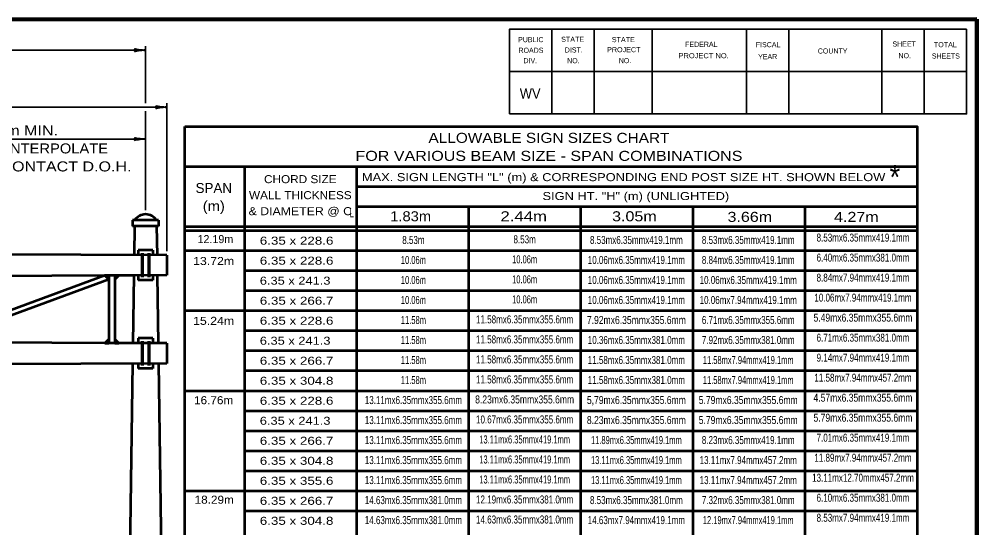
# Model space of a CAD drawing. Extents: x -34 to 822, y -23 to 521.
# Drawn here: x 527.6 to 814.9, y 362.2 to 514.7 of the extents above; entities that cross this region are included whole.
import ezdxf
from ezdxf.enums import TextEntityAlignment as Align

# ---------------------------------------------------------------- set-up
doc = ezdxf.new("R2010")
doc.units = 0
doc.header["$LTSCALE"] = 1.2
doc.layers.add('1', color=7, linetype='Continuous', lineweight=35)
doc.layers.add('61', color=7, linetype='Continuous', lineweight=35)

msp = doc.modelspace()

# ---------------------------------------------------------------- linework, layer by layer
at = {"layer": '1', "lineweight": 158}
msp.add_line((814.9, -11.36), (814.9, 514.74), dxfattribs=at)
at = {"layer": '1', "lineweight": 13}
msp.add_line((814.9, -11.36), (814.9, 514.74), dxfattribs=at)
at = {"layer": '1'}
for p, q in [((565.548, 489.542), (565.548, 506.642)), ((98.952, 505.442), (565.548, 505.442)), ((571.95, 445.142), (571.95, 489.542)), ((565.548, 457.442), (565.548, 487.142)), ((487.338, 478.781), (565.548, 478.781))]:
    msp.add_line(p, q, dxfattribs=at)
at = {"layer": '1', "lineweight": 53}
for p, q in [((577.354, 470.549), (796.954, 470.549)), ((595.354, 295.349), (595.354, 470.549)), ((628.954, 295.349), (628.954, 470.549)), ((628.954, 464.549), (796.954, 464.549)), ((628.954, 458.549), (796.954, 458.549)), ((662.554, 295.349), (662.554, 458.549)), ((696.154, 295.349), (696.154, 458.549)), ((729.754, 295.349), (729.754, 458.549)), ((763.354, 295.349), (763.354, 458.549)), ((569.448, 454.442), (561.648, 454.442)), ((561.648, 454.442), (561.648, 452.642)), ((569.448, 454.442), (569.448, 452.642)), ((569.448, 452.642), (561.648, 452.642)), ((562.248, 452.642), (562.125, 443.991)), ((568.848, 452.642), (568.971, 443.957)), ((577.354, 452.549), (796.954, 452.549)), ((577.354, 451.349), (796.954, 451.349)), ((567.75, 445.442), (563.346, 445.442)), ((563.346, 445.442), (563.346, 443.985)), ((567.75, 445.442), (567.75, 443.963)), ((577.354, 445.349), (796.954, 445.349)), ((571.95, 443.942), (333.15, 445.142)), ((571.95, 443.942), (571.95, 437.942)), ((554.538, 437.854), (502.338, 437.592)), ((553.339, 437.848), (502.338, 419.091)), ((556.338, 437.863), (554.538, 437.854)), ((554.538, 437.854), (554.538, 417.629)), ((562.038, 437.892), (556.338, 437.863)), ((556.338, 436.663), (557.538, 437.869)), ((556.338, 437.863), (556.338, 417.62)), ((562.038, 437.892), (561.75, 417.593)), ((571.95, 437.942), (562.038, 437.892)), ((563.346, 437.899), (563.346, 436.442)), ((567.75, 437.921), (567.75, 436.442)), ((569.057, 437.927), (569.346, 417.555)), ((595.354, 439.349), (796.954, 439.349)), ((554.538, 436.654), (503.538, 417.886)), ((567.75, 436.442), (563.346, 436.442)), ((595.354, 433.349), (796.954, 433.349)), ((577.354, 427.349), (796.954, 427.349)), ((595.354, 421.349), (796.954, 421.349)), ((554.538, 417.629), (502.338, 417.892)), ((553.339, 417.636), (554.538, 417.629)), ((556.338, 417.62), (554.538, 417.629)), ((561.75, 417.593), (556.338, 417.62)), ((571.95, 417.542), (561.75, 417.593)), ((567.75, 419.042), (563.346, 419.042)), ((563.346, 419.042), (563.346, 417.585)), ((567.75, 419.042), (567.75, 417.563)), ((571.95, 417.542), (571.95, 411.542)), ((595.354, 415.349), (796.954, 415.349)), ((571.95, 411.542), (333.15, 410.342)), ((561.663, 411.49), (559.59, 265.442)), ((563.346, 411.499), (563.346, 410.042)), ((567.75, 411.521), (567.75, 410.042)), ((569.431, 411.529), (571.505, 265.442)), ((567.75, 410.042), (563.346, 410.042)), ((595.354, 409.349), (796.954, 409.349)), ((577.354, 403.349), (796.954, 403.349)), ((595.354, 397.349), (796.954, 397.349)), ((595.354, 391.349), (796.954, 391.349)), ((595.354, 385.349), (796.954, 385.349)), ((595.354, 379.349), (796.954, 379.349)), ((577.354, 373.349), (796.954, 373.349)), ((595.354, 367.349), (796.954, 367.349))]:
    msp.add_line(p, q, dxfattribs=at)
at = {"layer": '1', "lineweight": 70}
for p, q in [((564.546, 444.542), (564.546, 437.342)), ((566.55, 444.542), (566.55, 437.342)), ((564.546, 418.142), (564.546, 410.942)), ((566.55, 418.142), (566.55, 410.942))]:
    msp.add_line(p, q, dxfattribs=at)
at = {"layer": '1', "lineweight": 158}
msp.add_lwpolyline([(814.9, 514.74), (23.2, 514.64), (23.3, -11.36)], dxfattribs=at)
at = {"layer": '1'}
msp.add_lwpolyline([(92.55, 488.342), (332.25, 488.342), (571.95, 488.342)], dxfattribs=at)
at = {"layer": '1', "lineweight": 53}
for points in [[(577.354, 482.549), (796.954, 482.549), (796.954, 295.349), (577.354, 295.349)], [(554.538, 436.654), (554.538, 437.854), (553.339, 437.848)], [(557.538, 417.614), (556.338, 418.82), (556.338, 417.62), (557.538, 417.614)]]:
    msp.add_lwpolyline(points, close=True, dxfattribs=at)
for points in [[(557.538, 437.869), (556.338, 437.863), (556.338, 436.663)], [(554.538, 417.629), (554.538, 418.829), (553.339, 417.635)]]:
    msp.add_lwpolyline(points, dxfattribs=at)
msp.add_arc((565.548, 452.364), 3.878, 32.40313, 147.59686, dxfattribs=at)
at = {"layer": '1', "lineweight": 40}
for centre, major_axis, ratio, start_param, end_param in [((564.203, 505.696), (2.108, -0.211), 0.07063, 3.1407148, 5.41811), ((564.203, 505.696), (2.108, -0.211), 0.07063, 3.1407148, 5.41811), ((564.238, 505.11), (2.143, 0.187), 0.122415, 0.8963533, 3.1415927), ((564.238, 505.11), (2.143, 0.187), 0.122415, 0.8963533, 3.1415927), ((570.605, 488.596), (2.108, -0.211), 0.07063, 3.1407148, 5.41811), ((570.605, 488.596), (2.108, -0.211), 0.07063, 3.1407148, 5.41811), ((570.605, 488.596), (2.108, -0.211), 0.07063, 3.1407148, 5.41811), ((570.64, 488.01), (2.143, 0.187), 0.122415, 0.8963533, 3.1415927), ((570.64, 488.01), (2.143, 0.187), 0.122415, 0.8963533, 3.1415927), ((570.64, 488.01), (2.143, 0.187), 0.122415, 0.8963533, 3.1415927), ((564.238, 478.449), (2.143, 0.187), 0.122415, 0.8963533, 3.1415927), ((564.238, 478.449), (2.143, 0.187), 0.122415, 0.8963533, 3.1415927), ((564.203, 479.035), (2.108, -0.211), 0.07063, 3.1407148, 5.41811), ((564.203, 479.035), (2.108, -0.211), 0.07063, 3.1407148, 5.41811)]:
    msp.add_ellipse(centre, major_axis=major_axis, ratio=ratio, start_param=start_param, end_param=end_param, dxfattribs=at)
at = {"layer": '61'}
for p, q in [((687.4, 511.74), (687.4, 486.34)), ((700.1, 511.74), (700.1, 486.34)), ((717.5, 511.74), (717.5, 486.34)), ((745.8, 511.74), (745.8, 486.34)), ((758.5, 511.74), (758.5, 486.34)), ((786.4, 511.74), (786.4, 486.34)), ((799.1, 511.74), (799.1, 486.34)), ((811.8, 499.04), (674.7, 499.04))]:
    msp.add_line(p, q, dxfattribs=at)
for points in [[(811.8, 511.74), (674.7, 511.74), (674.7, 486.34)], [(811.8, 511.74), (811.8, 486.34), (674.7, 486.34)]]:
    msp.add_lwpolyline(points, dxfattribs=at)

# ---------------------------------------------------------------- texts
at = {"layer": '1'}
for s, height, width, p in [('WV', 3.048, 0.95, (677.8, 490.94)), ('6.35 x 228.6', 2.4, 1.25, (599.804, 447.126)), ('6.35 x 228.6', 2.4, 1.25, (599.804, 441.126)), ('6.35 x 241.3', 2.4, 1.2, (599.804, 435.126)), ('6.35 x 266.7', 2.4, 1.25, (599.804, 429.126)), ('6.35 x 228.6', 2.4, 1.25, (599.804, 423.126)), ('6.35 x 241.3', 2.4, 1.2, (599.804, 417.126)), ('6.35 x 266.7', 2.4, 1.25, (599.804, 411.126)), ('6.35 x 304.8', 2.4, 1.25, (599.804, 405.126)), ('6.35 x 228.6', 2.4, 1.25, (599.804, 399.126)), ('6.35 x 241.3', 2.4, 1.2, (599.804, 393.126)), ('6.35 x 266.7', 2.4, 1.25, (599.804, 387.126)), ('6.35 x 304.8', 2.4, 1.25, (599.804, 381.126)), ('6.35 x 355.6', 2.4, 1.25, (599.804, 375.126)), ('6.35 x 266.7', 2.4, 1.25, (599.804, 369.126)), ('6.35 x 304.8', 2.4, 1.25, (599.804, 363.126))]:
    msp.add_text(s, height=height, dxfattribs=dict(at, width=width)).set_placement(p)
for s, height, width, p in [('1.83m MIN.', 3, 1.2, (526.826, 479.882)), ('ALLOWABLE SIGN SIZES CHART', 3, 1.15, (686.551, 477.653)), ('FOR LESS: INTERPOLATE', 3, 1.1, (526.826, 474.482)), ('FOR VARIOUS BEAM SIZE - SPAN COMBINATIONS', 3, 1.2, (686.551, 472.253)), ('TO MAX. OR CONTACT D.O.H.', 3, 1.2, (526.826, 469.082)), ('MAX. SIGN LENGTH "L" (m) & CORRESPONDING END POST SIZE HT. SHOWN BELOW', 2.4, 1.2, (708.936, 466.171)), ('*', 7.2, 0.85, (790.32, 463.792)), ('CHORD SIZE', 2.4, 1.1, (611.96, 465.568)), ('WALL THICKNESS', 2.4, 1.1, (611.96, 460.768)), ('SIGN HT. "H" (m) (UNLIGHTED)', 2.4, 1.2, (712.609, 460.502)), ('(m)', 3, 1.1, (586.003, 457.221)), ('& DIAMETER @ C', 2.4, 1.15, (611.96, 455.968)), ('L', 2.4, 0.75, (627.392, 455.332)), ('1.83m', 3, 1.1, (645.057, 454.14)), ('2.44m', 3, 1.25, (678.97, 454.14)), ('3.05m', 3, 1.2, (712.173, 454.14)), ('3.66m', 3, 1.2, (746.796, 453.963)), ('4.27m', 3, 1.2, (778.756, 453.963)), ('8.53m', 2.4, 0.75, (645.884, 447.335)), ('8.53m', 2.4, 0.75, (679.25, 447.518)), ('8.53mx6.35mmx419.1mm', 2.4, 0.75, (712.766, 447.338)), ('8.53mx6.35mmx419.1mm', 2.4, 0.75, (746.324, 447.338)), ('8.53mx6.35mmx419.1mm', 2.4, 0.75, (780.742, 448.045)), ('13.72m', 2.4, 1.15, (585.955, 441.025)), ('10.06m', 2.4, 0.7, (645.884, 441.335)), ('10.06m', 2.4, 0.7, (679.25, 441.518)), ('10.06mx6.35mmx419.1mm', 2.4, 0.75, (712.766, 441.338)), ('8.84mx6.35mmx419.1mm', 2.4, 0.75, (746.324, 441.338)), ('6.40mx6.35mmx381.0mm', 2.4, 0.75, (780.742, 442.045)), ('10.06m', 2.4, 0.7, (645.884, 435.335)), ('10.06m', 2.4, 0.7, (679.25, 435.518)), ('10.06mx6.35mmx419.1mm', 2.4, 0.75, (712.766, 435.338)), ('10.06mx6.35mmx419.1mm', 2.4, 0.75, (746.324, 435.338)), ('8.84mx7.94mmx419.1mm', 2.4, 0.75, (780.742, 436.045)), ('10.06m', 2.4, 0.7, (645.884, 429.335)), ('10.06m', 2.4, 0.7, (679.25, 429.518)), ('10.06mx6.35mmx419.1mm', 2.4, 0.75, (712.766, 429.338)), ('10.06mx7.94mmx419.1mm', 2.4, 0.75, (746.324, 429.338)), ('10.06mx7.94mmx419.1mm', 2.4, 0.75, (780.742, 430.045)), ('15.24m', 2.4, 1.15, (585.955, 423.087)), ('11.58m', 2.4, 0.65, (645.884, 423.335)), ('11.58mx6.35mmx355.6mm', 2.4, 0.75, (679.25, 423.518)), ('7.92mx6.35mmx355.6mm', 2.4, 0.8, (712.766, 423.338)), ('6.71mx6.35mmx355.6mm', 2.4, 0.75, (746.324, 423.338)), ('5.49mx6.35mmx355.6mm', 2.4, 0.8, (780.742, 424.045)), ('11.58m', 2.4, 0.65, (645.884, 417.335)), ('11.58mx6.35mmx355.6mm', 2.4, 0.75, (679.25, 417.518)), ('10.36mx6.35mmx381.0mm', 2.4, 0.75, (712.766, 417.338)), ('7.92mx6.35mmx381.0mm', 2.4, 0.75, (746.324, 417.338)), ('6.71mx6.35mmx381.0mm', 2.4, 0.75, (780.742, 418.045)), ('11.58m', 2.4, 0.65, (645.884, 411.335)), ('11.58mx6.35mmx355.6mm', 2.4, 0.75, (679.25, 411.518)), ('11.58mx6.35mmx381.0mm', 2.4, 0.75, (712.766, 411.338)), ('11.58mx7.94mmx419.1mm', 2.4, 0.7, (746.324, 411.338)), ('9.14mx7.94mmx419.1mm', 2.4, 0.75, (780.742, 412.045)), ('11.58mx6.35mmx355.6mm', 2.4, 0.75, (679.25, 405.518)), ('11.58mx7.94mmx457.2mm', 2.4, 0.75, (780.742, 406.045)), ('11.58m', 2.4, 0.65, (645.884, 405.335)), ('11.58mx6.35mmx381.0mm', 2.4, 0.75, (712.766, 405.338)), ('11.58mx7.94mmx419.1mm', 2.4, 0.7, (746.324, 405.338)), ('4.57mx6.35mmx355.6mm', 2.4, 0.8, (780.742, 400.045)), ('16.76m', 2.4, 1.1, (585.955, 399.289)), ('13.11mx6.35mmx355.6mm', 2.4, 0.75, (645.884, 399.335)), ('8.23mx6.35mmx355.6mm', 2.4, 0.8, (679.25, 399.518)), ('5,79mx6.35mmx355.6mm', 2.4, 0.8, (712.766, 399.338)), ('5.79mx6.35mmx355.6mm', 2.4, 0.8, (746.324, 399.338)), ('5.79mx6.35mmx355.6mm', 2.4, 0.8, (780.742, 394.045)), ('13.11mx6.35mmx355.6mm', 2.4, 0.75, (645.884, 393.335)), ('10.67mx6.35mmx355.6mm', 2.4, 0.75, (679.25, 393.518)), ('8.23mx6.35mmx355.6mm', 2.4, 0.8, (712.766, 393.338)), ('5.79mx6.35mmx355.6mm', 2.4, 0.8, (746.324, 393.338)), ('13.11mx6.35mmx355.6mm', 2.4, 0.75, (645.884, 387.335)), ('13.11mx6.35mmx419.1mm', 2.4, 0.7, (679.25, 387.518)), ('11.89mx6.35mmx419.1mm', 2.4, 0.7, (712.766, 387.338)), ('8.23mx6.35mmx419.1mm', 2.4, 0.75, (746.324, 387.338)), ('7.01mx6.35mmx419.1mm', 2.4, 0.75, (780.742, 388.045)), ('13.11mx6.35mmx355.6mm', 2.4, 0.75, (645.884, 381.335)), ('13.11mx6.35mmx419.1mm', 2.4, 0.7, (679.25, 381.518)), ('13.11mx6.35mmx419.1mm', 2.4, 0.7, (712.766, 381.338)), ('13.11mx7.94mmx457.2mm', 2.4, 0.75, (746.324, 381.338)), ('11.89mx7.94mmx457.2mm', 2.4, 0.75, (780.742, 382.045)), ('13.11mx6.35mmx355.6mm', 2.4, 0.75, (645.884, 375.335)), ('13.11mx6.35mmx419.1mm', 2.4, 0.7, (679.25, 375.518)), ('13.11mx6.35mmx419.1mm', 2.4, 0.7, (712.766, 375.338)), ('13.11mx7.94mmx457.2mm', 2.4, 0.75, (746.324, 375.338)), ('13.11mx12.70mmx457.2mm', 2.4, 0.75, (780.742, 376.045)), ('18.29m', 2.4, 1.1, (586.133, 369.452)), ('14.63mx6.35mmx381.0mm', 2.4, 0.75, (645.884, 369.335)), ('12.19mx6.35mmx381.0mm', 2.4, 0.75, (679.25, 369.518)), ('8.53mx6.35mmx381.0mm', 2.4, 0.75, (712.766, 369.338)), ('7.32mx6.35mmx381.0mm', 2.4, 0.75, (746.324, 369.338)), ('6.10mx6.35mmx381.0mm', 2.4, 0.75, (780.742, 370.045)), ('14.63mx6.35mmx381.0mm', 2.4, 0.75, (645.884, 363.335)), ('14.63mx6.35mmx381.0mm', 2.4, 0.75, (679.25, 363.518)), ('14.63mx7.94mmx419.1mm', 2.4, 0.75, (712.766, 363.338)), ('12.19mx7.94mmx419.1mm', 2.4, 0.7, (746.324, 363.338)), ('8.53mx7.94mmx419.1mm', 2.4, 0.75, (780.742, 364.045))]:
    msp.add_text(s, height=height, dxfattribs=dict(at, width=width)).set_placement(p, align=Align.CENTER)
for s, height, p in [('SPAN', 3, (586.003, 462.621)), ('12.19m', 2.4, (586.488, 447.596))]:
    msp.add_text(s, height=height, dxfattribs=at).set_placement(p, align=Align.CENTER)
at = {"layer": '61'}
for s, height, rotation, p in [('PUBLIC', 1.525, 0.033, (677.3, 507.84)), ('ROADS', 1.525, 0.124, (677.4, 504.64)), ('DIST.', 1.525, 0.056, (691.3, 504.74)), ('FEDERAL', 1.523, 0.007, (727.4, 506.44)), ('FISCAL', 1.525, 359.942, (748.6, 506.34)), ('COUNTY', 1.523, 0.069, (767.2, 504.44)), ('SHEET', 1.525, 0.059, (789.6, 506.54)), ('DIV.', 1.525, 359.932, (678.9, 501.54)), ('YEAR', 1.523, 0.105, (749.3, 502.74)), ('SHEETS', 1.523, 359.959, (801.4, 502.94))]:
    msp.add_text(s, height=height, rotation=rotation, dxfattribs=at).set_placement(p)
for s, rotation, width, p in [('STATE', 0.059, 1.05, (690.2, 507.94)), ('STATE', 0.059, 1.05, (705.4, 507.84)), ('PROJECT', 359.908, 1.05, (704, 504.84)), ('TOTAL', 359.926, 1.05, (802, 506.34)), ('NO.', 359.852, 0.9, (692, 501.54)), ('NO.', 0.225, 0.9, (707.5, 501.54)), ('PROJECT NO.', 359.922, 1.1, (725.4, 503.04)), ('NO.', 359.852, 0.9, (791.4, 503.04))]:
    msp.add_text(s, height=1.525, rotation=rotation, dxfattribs=dict(at, width=width)).set_placement(p)

doc.saveas('drawing.dxf')
